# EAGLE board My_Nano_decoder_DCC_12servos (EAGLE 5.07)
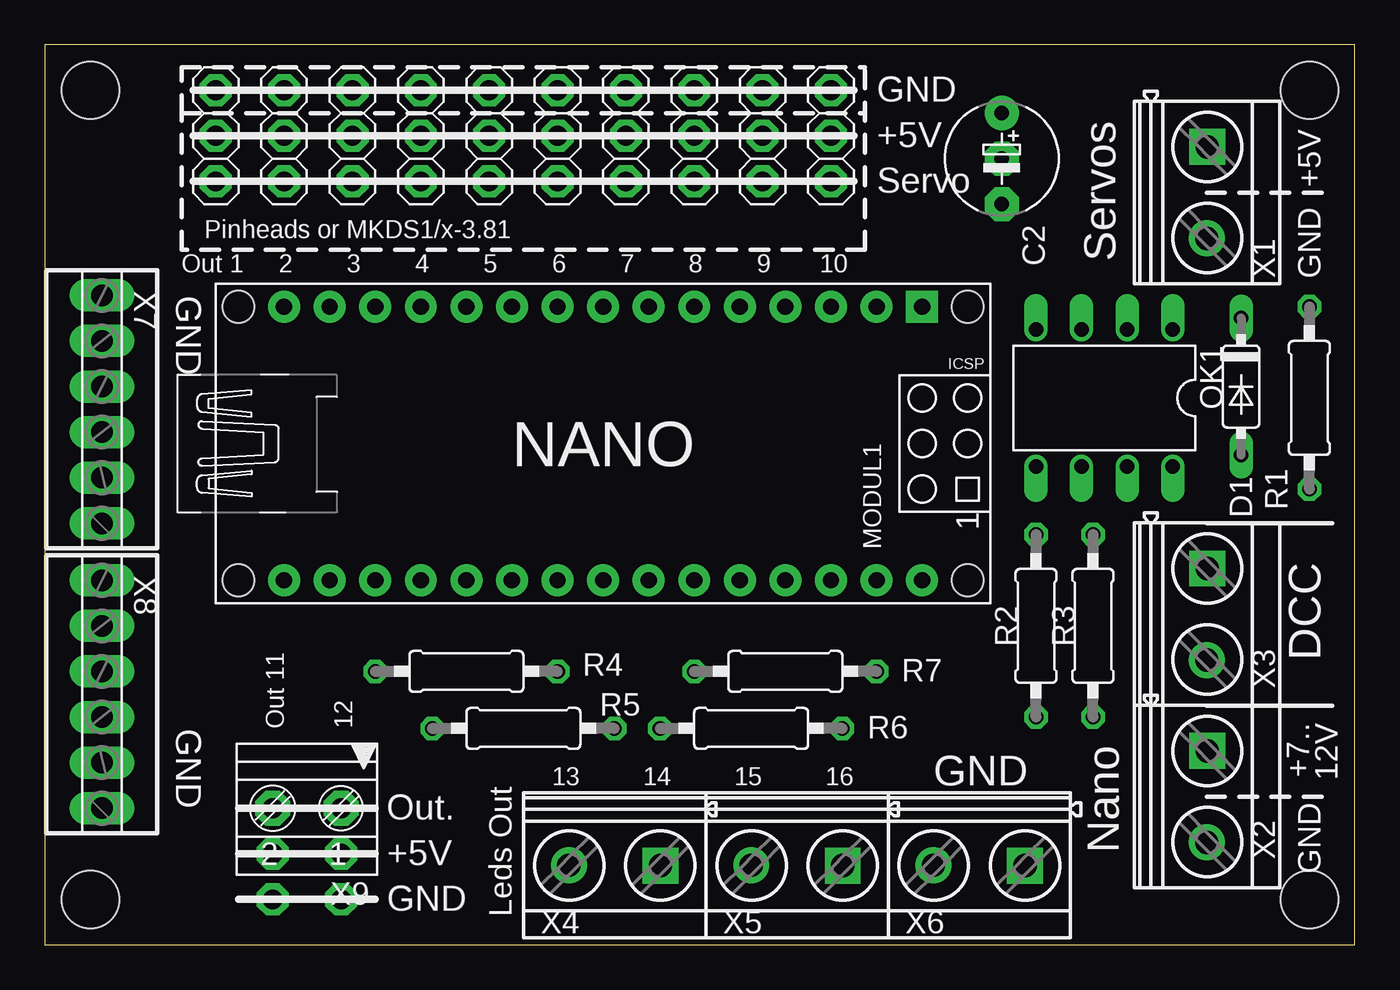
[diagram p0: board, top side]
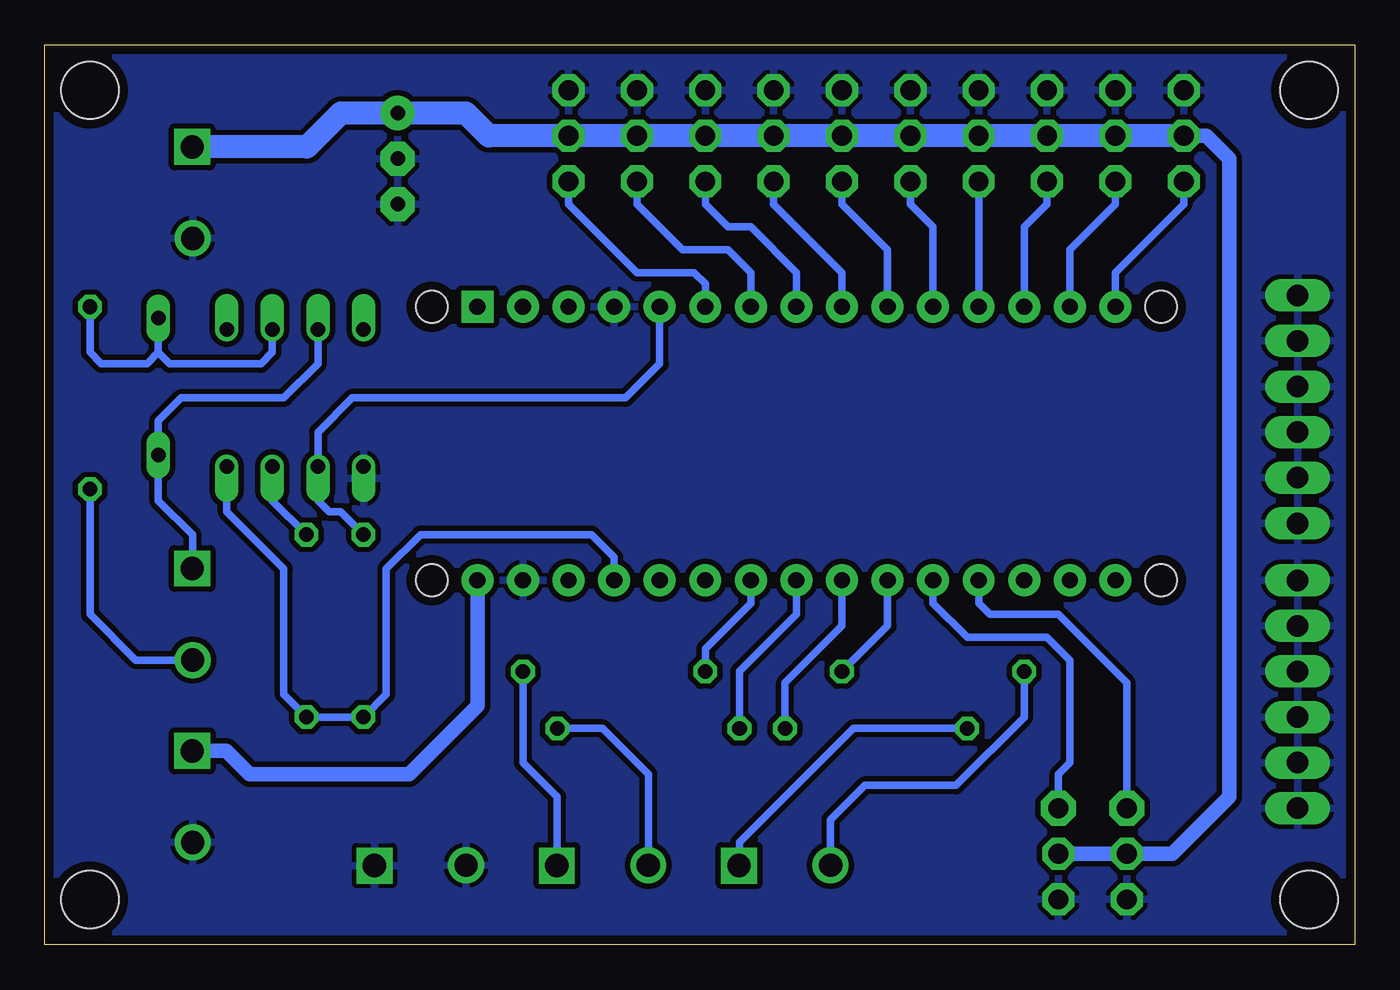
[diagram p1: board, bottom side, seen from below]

Size 73 x 50.15 mm. Coordinates in mm from the lower left corner, seen from the top.
Outline: 0,0 73,0 73,50.15 0,50.15 0,0
Copper layers (1*16): Top 0.035mm / dielectric 1.5mm / Bottom 0.035mm
Design rules "default *": minimum track width 10mil, minimum drill 24mil, track to track 8mil, track to pad 8mil, pad to pad 8mil, via to via 8mil, smd to smd 8mil, copper to edge 20mil, drill to drill 10mil, minimum pad ring 10mil, minimum via ring 8mil, stop-mask expansion 4mil, vias tented up to drill 0mil, thermal gap 10mil
Holes 3.2 mm at 2.54,47.62 2.54,2.54 70.48,2.54 70.48,47.62

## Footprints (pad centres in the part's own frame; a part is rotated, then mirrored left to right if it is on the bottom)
E2.5/5-6 = drill 0.813 pad 1.905 round: + -2.54,0 | drill 0.813 pad 1.905 octagon: - 2.54,0; -1 0,0
DO35-7 = drill 0.813 long: A 3.81,0; C -3.81,0
1X03 = drill 1.1 pad 1.778 octagon: 1 -2.54,0; 2 0,0; 3 2.54,0
ARDUINO_NANO2 = drill 0.914 pad 1.778 square: J1.1 -7.62,17.78 | drill 0.914 pad 1.778 round: J1.2 -7.62,15.24; J1.3 -7.62,12.7; J1.4 -7.62,10.16; J1.5 -7.62,7.62; J1.6 -7.62,5.08; J1.7 -7.62,2.54; J1.8 -7.62,0; J1.9 -7.62,-2.54; J1.10 -7.62,-5.08; J1.11 -7.62,-7.62; J1.12 -7.62,-10.16; J1.13 -7.62,-12.7; J1.14 -7.62,-15.24; J1.15 -7.62,-17.78; J2.1 7.62,17.78; J2.2 7.62,15.24; J2.3 7.62,12.7; J2.4 7.62,10.16; J2.5 7.62,7.62; J2.6 7.62,5.08; J2.7 7.62,2.54; J2.8 7.62,0; J2.9 7.62,-2.54; J2.10 7.62,-5.08; J2.11 7.62,-7.62; J2.12 7.62,-10.16; J2.13 7.62,-12.7; J2.14 7.62,-15.24; J2.15 7.62,-17.78 | hole 1.778: -7.62,-20.32; 7.62,-20.32; 7.62,20.32; -7.62,20.32
DIL08 = drill 0.813 offset: 1 -3.81,-3.81; 2 -1.27,-3.81; 3 1.27,-3.81; 4 3.81,-3.81; 5 3.81,3.81; 6 1.27,3.81; 7 -1.27,3.81; 8 -3.81,3.81
0207/10 = drill 0.813 octagon: 1 -5.08,0; 2 5.08,0
PAD = drill 1.1 pad 1.778 octagon:  0,0
MKDSN1,5/2-5,08 = drill 1.3 pad 2 square: 1 -2.561,0.025 | drill 1.3 pad 2 round: 2 2.54,0
6POL254 = drill 1.2 pad 1.778 long: 1 -6.35,0; 2 -3.81,0; 3 -1.27,0; 4 1.27,0; 5 3.81,0; 6 6.35,0
2POL381 = drill 1.1 pad 1.93 octagon: 1 0,0; 2 3.81,0

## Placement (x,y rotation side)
C2  330µ/35V  [E2.5/5-6]  53.34,43.81 270 top
D1  1N4148  [DO35-7]  66.67,31.11 270 top
JP1  [1X03]  9.53,45.09 90 top
JP2  [1X03]  13.34,45.09 90 top
JP3  [1X03]  17.14,45.09 90 top
JP4  [1X03]  20.95,45.09 90 top
JP5  [1X03]  24.77,45.09 90 top
JP6  [1X03]  28.57,45.09 90 top
JP7  [1X03]  32.38,45.09 90 top
JP8  [1X03]  36.2,45.09 90 top
JP9  [1X03]  40.01,45.09 90 top
JP10  [1X03]  43.81,45.09 90 top
MODUL1  ARDUINO_NANO2  [ARDUINO_NANO2]  31.11,27.94 270 top
OK1  6N137  [DIL08]  59.05,30.48 180 top
R1  1k  [0207/10]  70.48,30.48 90 top
R2  10k  [0207/10]  55.24,17.78 270 top
R3  10k  [0207/10]  58.42,17.78 270 top
R4  560  [0207/10]  23.5,15.24 0 top
R5  560  [0207/10]  26.67,12.06 0 top
R6  560  [0207/10]  39.37,12.06 180 top
R7  560  [0207/10]  41.27,15.24 180 top
U$1  PAD  [PAD]  12.7,2.54 0 top
U$2  PAD  [PAD]  12.7,5.08 0 top
U$3  PAD  [PAD]  16.51,2.54 0 top
U$4  PAD  [PAD]  16.51,5.08 0 top
X1  MKDSN1,5/2-5,08  [MKDSN1,5/2-5,08]  64.77,41.91 270 top
X2  MKDSN1,5/2-5,08  [MKDSN1,5/2-5,08]  64.77,8.26 270 top
X3  MKDSN1,5/2-5,08  [MKDSN1,5/2-5,08]  64.77,18.41 270 top
X4  MKDSN1,5/2-5,08  [MKDSN1,5/2-5,08]  31.75,4.45 180 top
X5  MKDSN1,5/2-5,08  [MKDSN1,5/2-5,08]  41.91,4.45 180 top
X6  MKDSN1,5/2-5,08  [MKDSN1,5/2-5,08]  52.07,4.45 180 top
X7  [6POL254]  3.17,29.84 90 top
X8  [6POL254]  3.17,13.97 90 top
X9  MKDS1/2-3,81  [2POL381]  16.51,7.62 180 top

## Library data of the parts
C2 = rcl_perso
D1 = diode
JP1-JP10 U$1-U$4 = my-pinhead
MODUL1 = arduino_Nano; ANZAHL: 2; MODUL: TRUE; STECKX0: -76200; STECKX1: 76200; STECKY0: 177800; STECKY1: 177800
OK1 = optocoupler
R1-R7 = rcl
X1-X6 = con-phoenix-508
X7 X8 = con-phoenix-254
X9 = my-conn-phoenix-381

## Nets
3V3: MODUL1.J2.14
@1_0: JP1.1 MODUL1.J1.15
@1_1: JP2.1 MODUL1.J1.14
@1_2: JP3.1 MODUL1.J1.13
@1_3: JP4.1 MODUL1.J1.12
@1_4: JP5.1 MODUL1.J1.11
@1_5: JP6.1 MODUL1.J1.10
@1_6: JP7.1 MODUL1.J1.9
@1_7: JP8.1 MODUL1.J1.8
@2_0: JP9.1 MODUL1.J1.7
@2_1: JP10.1 MODUL1.J1.6
@2_2: MODUL1.J2.12 X9.2
@2_3: MODUL1.J2.11 X9.1
@2_4: MODUL1.J2.10 R4.2
@2_5: MODUL1.J2.9 R5.2
@2_6: MODUL1.J2.8 R6.2
@2_7: MODUL1.J2.7 R7.2
AREF: MODUL1.J2.13
BROWN_TRACK: R1.1 X3.2
DCC: MODUL1.J1.5 OK1.6 R2.1
GND: C2.- C2.-1 JP1.3 JP2.3 JP3.3 JP4.3 JP5.3 JP6.3 JP7.3 JP8.3 JP9.3 JP10.3 MODUL1.J1.4 MODUL1.J2.2 OK1.5 U$1. U$3. X1.2 X2.2 X6.1 X6.2 X7.1 X7.2 X7.3 X7.4 X7.5 X7.6 X8.1 X8.2 X8.3 X8.4 X8.5 X8.6
N$2: D1.C OK1.2 R1.2
N$4: OK1.7 R3.1
N$7: R4.1 X4.2
N$8: R5.1 X4.1
N$9: R6.1 X5.2
N$10: R7.1 X5.1
RED_TRACK: D1.A OK1.3 X3.1
VCC: MODUL1.J2.4 OK1.8 R2.2 R3.2
VCCIO: C2.+ JP1.2 JP2.2 JP3.2 JP4.2 JP5.2 JP6.2 JP7.2 JP8.2 JP9.2 JP10.2 U$2. U$4. X1.1
VIN: MODUL1.J2.1 X2.1

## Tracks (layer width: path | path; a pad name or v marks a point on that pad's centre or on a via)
@1_0
  Bottom 0.406: MODUL1.J1.15 13.34,37.47 9.53,41.27 JP1.1
@1_1
  Bottom 0.406: MODUL1.J1.14 15.88,38.73 13.34,41.27 JP2.1
@1_2
  Bottom 0.406: JP3.1 17.14,41.27 18.41,40.01 MODUL1.J1.13
@1_3
  Bottom 0.406: MODUL1.J1.12 JP4.1
@1_4
  Bottom 0.406: JP5.1 24.77,41.27 23.5,40.01 MODUL1.J1.11
@1_5
  Bottom 0.406: JP6.1 28.57,41.27 26.04,38.73 MODUL1.J1.10
@1_6
  Bottom 0.406: JP7.1 32.38,41.27 28.57,37.47 MODUL1.J1.9
@1_7
  Bottom 0.406: JP8.1 36.2,41.27 34.92,40.01 33.66,40.01 31.11,37.47 MODUL1.J1.8
@2_0
  Bottom 0.406: JP9.1 40.01,41.27 37.47,38.73 34.92,38.73 33.66,37.47 MODUL1.J1.7
@2_1
  Bottom 0.406: JP10.1 43.81,41.27 40.01,37.47 36.83,37.47 36.2,36.83 MODUL1.J1.6
@2_2
  Bottom 0.406: MODUL1.J2.12 20.95,19.05 20.32,18.41 16.51,18.41 12.7,14.61 X9.2
@2_3
  Bottom 0.406: MODUL1.J2.11 23.5,19.05 21.59,17.14 17.14,17.14 15.88,15.88 15.88,10.16 16.51,9.53 X9.1
@2_4
  Bottom 0.406: MODUL1.J2.10 26.04,17.78 R4.2
@2_5
  Bottom 0.406: MODUL1.J2.9 28.57,17.78 31.75,14.61 R5.2
@2_6
  Bottom 0.406: MODUL1.J2.8 31.11,18.41 34.29,15.24 R6.2
@2_7
  Bottom 0.406: MODUL1.J2.7 33.66,19.05 36.2,16.51 R7.2
BROWN_TRACK
  Bottom 0.406: R1.1 70.48,18.41 67.94,15.88 X3.2
DCC
  Bottom 0.406: MODUL1.J1.5 38.73,32.38 40.64,30.48 55.88,30.48 57.78,28.57 OK1.6 57.78,24.77 57.15,24.13 56.52,24.13 R2.1
GND
  pour Bottom (isolate 0.305): 0,50.16 73.03,50.16 73.03,0 0,0
N$2
  Bottom 0.406: 66.67,33.02 D1.C | 66.67,33.02 67.31,32.38 69.85,32.38 70.48,33.02 R1.2 | OK1.2 60.33,33.02 60.96,32.38 66.04,32.38 66.67,33.02
N$4
  Bottom 0.406: OK1.7 60.33,24.77 R3.1
N$7
  Bottom 0.406: R4.1 18.41,12.7 22.23,8.89 27.3,8.89 29.21,6.99 X4.2
N$8
  Bottom 0.406: R5.1 27.94,12.06 34.29,5.71 34.29,4.44 X4.1
N$9
  Bottom 0.406: R6.1 41.91,12.06 39.37,9.53 X5.2
N$10
  Bottom 0.406: R7.1 46.35,10.16 44.45,8.26 44.45,4.44 X5.1
RED_TRACK
  Bottom 0.406: OK1.3 57.78,32.38 59.69,30.48 65.41,30.48 66.67,29.21 D1.A 66.67,24.77 64.77,22.86 64.77,21 X3.1
VCC
  Bottom 0.406: MODUL1.J2.4 41.27,21.59 42.55,22.86 52.07,22.86 53.98,20.95 53.98,13.97 R2.2 R3.2 59.69,13.97 59.69,20.95 62.87,24.13 OK1.8
VCCIO
  Bottom 0.813: JP1.2 8.26,45.09 6.99,43.81 6.99,8.26 10.16,5.08 U$2. U$4.
  Bottom 1.27: JP1.2 JP2.2 JP3.2 JP4.2 JP5.2 JP6.2 JP7.2 JP8.2 JP9.2 JP10.2 48.26,45.09 49.53,46.35 C2.+ 56.52,46.35 58.4,44.47 X1.1
VIN
  Bottom 0.813: MODUL1.J2.1 48.9,13.34 52.7,9.53 61.59,9.53 62.89,10.82 X2.1

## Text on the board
tNames: GND | +5V | Servo | +5V | Pinheads or MKDS1/x-3.81 | Servos | Out 1 | 2 | 3 | 4 | 5 | 6 | 7 | 8 | 9 | 10 | GND | GND | DCC | GND | Out 11 | 12 | +7.. | 12V | Nano | 13 | 14 | 15 | 16 | GND | GND | Out. | +5V | GND | Leds Out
